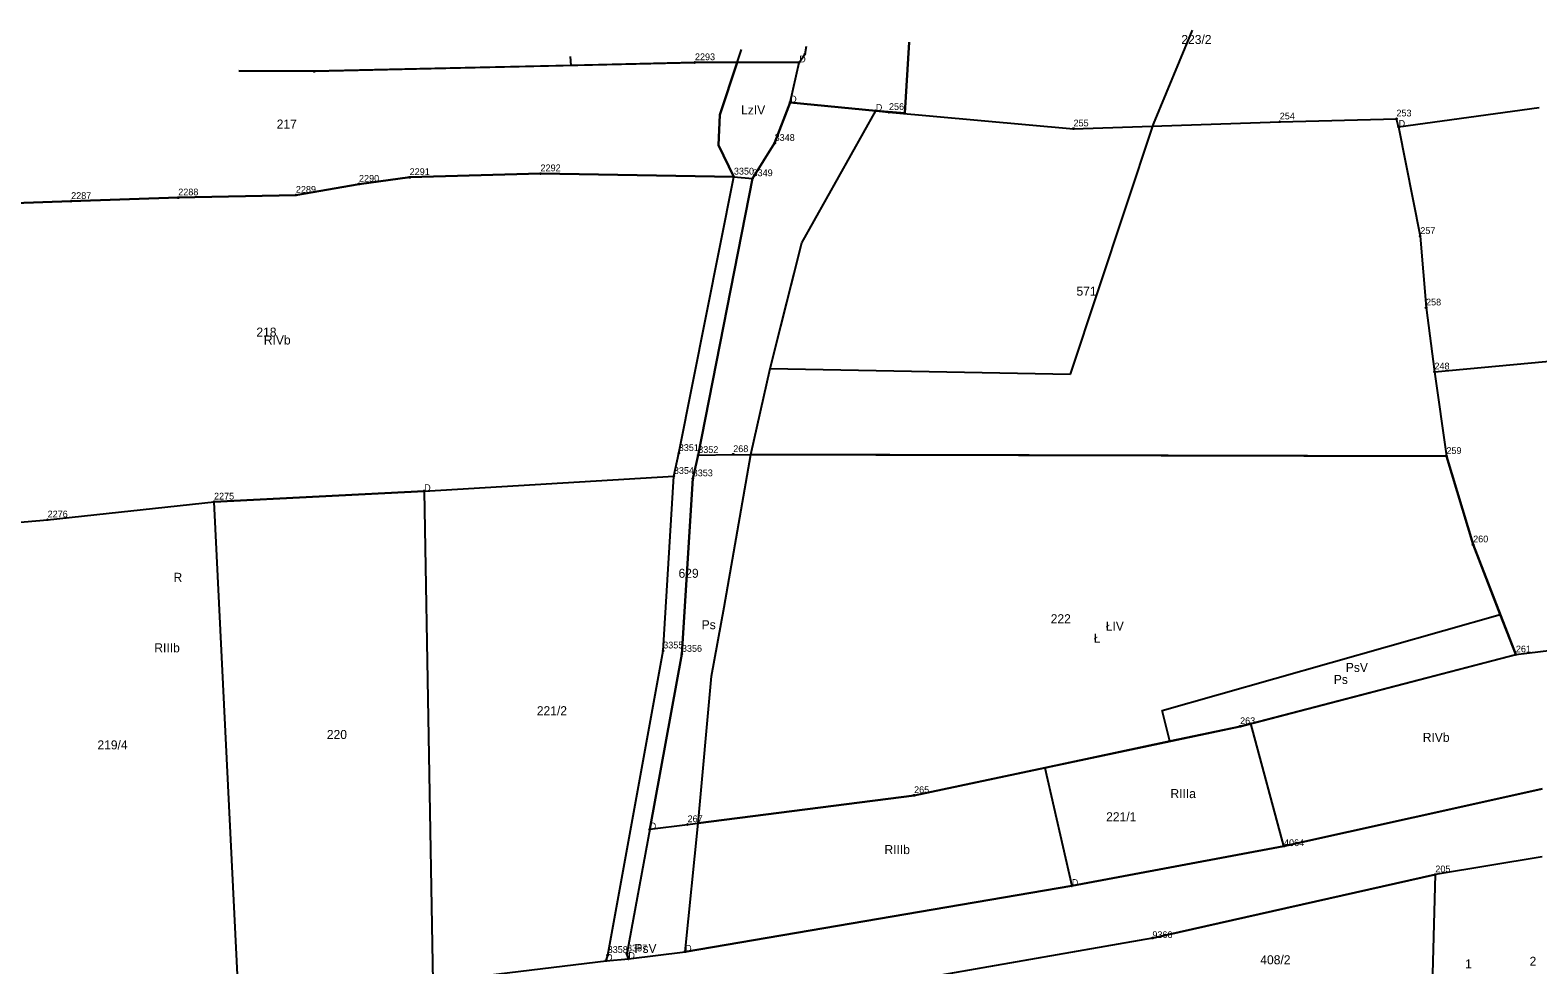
# Model space of a CAD drawing. Extents: x 7467189 to 7469366, y 5491487 to 5492734.
# Drawn here: x 7468735 to 7468985.9, y 5491680.6 to 5491836.1 of the extents above; entities that cross this region are included whole.
import ezdxf

# ---------------------------------------------------------------- set-up
doc = ezdxf.new("R2010")
doc.units = 0
for name, color, linetype in [('203-punkt graniczny', 7, 'Continuous'), ('203-punkt graniczny-Atr103', 7, 'Continuous'), ('209-oznaczenie konturu klasyfikacyjnego', 7, 'Continuous'), ('210-oznaczenie konturu użytku gruntowego', 7, 'Continuous'), ('211-numer działki ewidencyjnej', 7, 'Continuous'), ('217-kontur klasyfikacyjny', 7, 'Continuous'), ('218-kontur użytku gruntowego', 7, 'Continuous'), ('219-działka ewidencyjna', 7, 'Continuous'), ('Punkt budynku-Atr104', 7, 'Continuous')]:
    doc.layers.add(name, color=color, linetype=linetype)

# ---------------------------------------------------------------- blocks, each defined once
blk = doc.blocks.new('203')
blk.add_circle((0, 0), 0.09)

msp = doc.modelspace()

# ---------------------------------------------------------------- linework, layer by layer
at = {"layer": '217-kontur klasyfikacyjny'}
for points in [[(7468921.89, 5491820.44), (7468928.4, 5491836.08)], [(7468852.63, 5491830.7), (7468853.33, 5491832.89)], [(7468881.22, 5491834.07), (7468880.51, 5491822.25)], [(7468824.85, 5491831.68), (7468824.91, 5491830.22)], [(7468845.59, 5491830.7), (7468824.91, 5491830.22)], [(7468852.63, 5491830.7), (7468845.59, 5491830.7)], [(7468852.63, 5491830.7), (7468849.74, 5491821.99)], [(7468862.95, 5491830.71), (7468852.63, 5491830.7)], [(7468861.45, 5491824.07), (7468862.95, 5491830.71)], [(7468782.24, 5491829.24), (7468769.68, 5491829.33)], [(7468824.91, 5491830.22), (7468782.24, 5491829.24)], [(7468858.85, 5491817.28), (7468861.45, 5491824.07)], [(7468875.69, 5491822.68), (7468861.45, 5491824.07)], [(7468849.74, 5491821.99), (7468849.53, 5491816.93)], [(7468863.39, 5491800.69), (7468875.69, 5491822.68)], [(7468880.51, 5491822.25), (7468875.69, 5491822.68)], [(7468908.09, 5491778.88), (7468921.89, 5491820.44)], [(7468849.53, 5491816.93), (7468852.07, 5491811.68)], [(7468855.18, 5491811.41), (7468858.85, 5491817.28)], [(7468779.18, 5491808.65), (7468789.69, 5491810.49)], [(7468789.69, 5491810.49), (7468798.12, 5491811.6)], [(7468798.12, 5491811.6), (7468819.9, 5491812.23)], [(7468819.9, 5491812.23), (7468852.07, 5491811.68)], [(7468842.9, 5491765.7), (7468852.07, 5491811.68)], [(7468855.18, 5491811.41), (7468846.13, 5491765.38)], [(7468852.07, 5491811.68), (7468855.18, 5491811.41)], [(7468741.79, 5491807.63), (7468759.61, 5491808.22)], [(7468759.61, 5491808.22), (7468779.18, 5491808.65)], [(7468721.34, 5491806.93), (7468741.79, 5491807.63)], [(7468858.1, 5491779.82), (7468863.39, 5491800.69)], [(7468854.88, 5491765.51), (7468858.1, 5491779.82)], [(7468858.1, 5491779.82), (7468908.09, 5491778.88)], [(7468842.08, 5491761.89), (7468842.9, 5491765.7)], [(7468846.13, 5491765.38), (7468845.22, 5491761.49)], [(7468850.48, 5491740.07), (7468854.88, 5491765.51)], [(7468970.64, 5491765.2), (7468854.88, 5491765.51)], [(7468975.09, 5491750.5), (7468970.64, 5491765.2)], [(7468800.54, 5491759.42), (7468842.08, 5491761.89)], [(7468840.31, 5491732.85), (7468842.08, 5491761.89)], [(7468845.22, 5491761.49), (7468843.42, 5491732.29)], [(7468737.87, 5491754.64), (7468765.56, 5491757.63)], [(7468765.56, 5491757.63), (7468800.54, 5491759.42)], [(7468732.01, 5491754.12), (7468737.87, 5491754.64)], [(7468979.61, 5491738.87), (7468975.09, 5491750.5)], [(7468848.33, 5491728.61), (7468850.48, 5491740.07)], [(7468923.36, 5491722.88), (7468979.61, 5491738.87)], [(7468982.2, 5491732.21), (7468979.61, 5491738.87)], [(7468831.07, 5491682.2), (7468840.31, 5491732.85)], [(7468982.2, 5491732.21), (7468989.94, 5491733.19)], [(7468843.42, 5491732.29), (7468838.07, 5491703.14)], [(7468938.1, 5491720.73), (7468982.2, 5491732.21)], [(7468846.13, 5491704.18), (7468848.33, 5491728.61)], [(7468924.64, 5491717.8), (7468923.36, 5491722.88)], [(7468936.31, 5491720.27), (7468924.64, 5491717.8)], [(7468938.1, 5491720.73), (7468936.31, 5491720.27)], [(7468943.61, 5491700.35), (7468938.1, 5491720.73)], [(7468924.64, 5491717.8), (7468903.79, 5491713.39)], [(7468903.79, 5491713.39), (7468882.06, 5491708.79)], [(7468903.79, 5491713.39), (7468908.3, 5491693.74)], [(7468975.85, 5491707.51), (7468986.59, 5491709.9)], [(7468882.06, 5491708.79), (7468846.13, 5491704.18)], [(7468943.61, 5491700.35), (7468975.85, 5491707.51)], [(7468838.07, 5491703.14), (7468834.28, 5491682.45)], [(7468843.96, 5491682.79), (7468846.13, 5491704.18)], [(7468908.3, 5491693.74), (7468943.61, 5491700.35)], [(7468986.6, 5491698.59), (7468968.8, 5491695.61)], [(7468968.8, 5491695.61), (7468921.71, 5491685.05)], [(7468967.85, 5491658.42), (7468968.8, 5491695.61)], [(7468843.96, 5491682.79), (7468908.3, 5491693.74)], [(7468921.71, 5491685.05), (7468864.94, 5491675.1)], [(7468834.28, 5491682.45), (7468834.52, 5491681.59)], [(7468834.52, 5491681.59), (7468843.96, 5491682.79)], [(7468801.97, 5491677.77), (7468830.8, 5491681.29)], [(7468830.8, 5491681.29), (7468831.07, 5491682.2)]]:
    msp.add_lwpolyline(points, dxfattribs=at)
at = {"layer": '218-kontur użytku gruntowego'}
for points in [[(7468852.63, 5491830.7), (7468853.33, 5491832.89)], [(7468880.51, 5491822.25), (7468881.22, 5491834.07)], [(7468845.59, 5491830.7), (7468824.91, 5491830.22)], [(7468852.63, 5491830.7), (7468845.59, 5491830.7)], [(7468849.74, 5491821.99), (7468852.63, 5491830.7)], [(7468782.24, 5491829.24), (7468769.68, 5491829.33)], [(7468824.91, 5491830.22), (7468782.24, 5491829.24)], [(7468861.45, 5491824.07), (7468858.85, 5491817.28)], [(7468875.69, 5491822.68), (7468861.45, 5491824.07)], [(7468849.53, 5491816.93), (7468849.74, 5491821.99)], [(7468863.39, 5491800.69), (7468875.69, 5491822.68)], [(7468875.69, 5491822.68), (7468880.51, 5491822.25)], [(7468852.07, 5491811.68), (7468849.53, 5491816.93)], [(7468858.85, 5491817.28), (7468855.18, 5491811.41)], [(7468789.69, 5491810.49), (7468779.18, 5491808.65)], [(7468798.12, 5491811.6), (7468789.69, 5491810.49)], [(7468819.9, 5491812.23), (7468798.12, 5491811.6)], [(7468852.07, 5491811.68), (7468819.9, 5491812.23)], [(7468842.9, 5491765.7), (7468852.07, 5491811.68)], [(7468855.18, 5491811.41), (7468846.13, 5491765.38)], [(7468852.07, 5491811.68), (7468855.18, 5491811.41)], [(7468759.61, 5491808.22), (7468741.79, 5491807.63)], [(7468779.18, 5491808.65), (7468759.61, 5491808.22)], [(7468741.79, 5491807.63), (7468721.34, 5491806.93)], [(7468860.89, 5491790.84), (7468863.39, 5491800.69)], [(7468858.1, 5491779.82), (7468860.89, 5491790.84)], [(7468854.88, 5491765.51), (7468858.1, 5491779.82)], [(7468842.08, 5491761.89), (7468842.9, 5491765.7)], [(7468846.13, 5491765.38), (7468845.22, 5491761.49)], [(7468850.48, 5491740.07), (7468854.88, 5491765.51)], [(7468970.64, 5491765.2), (7468854.88, 5491765.51)], [(7468975.09, 5491750.5), (7468970.64, 5491765.2)], [(7468840.31, 5491732.85), (7468842.08, 5491761.89)], [(7468845.22, 5491761.49), (7468843.42, 5491732.29)], [(7468979.61, 5491738.87), (7468975.09, 5491750.5)], [(7468848.33, 5491728.61), (7468850.48, 5491740.07)], [(7468923.36, 5491722.88), (7468979.61, 5491738.87)], [(7468982.2, 5491732.21), (7468979.61, 5491738.87)], [(7468831.07, 5491682.2), (7468840.31, 5491732.85)], [(7468843.42, 5491732.29), (7468838.07, 5491703.14)], [(7468938.1, 5491720.73), (7468982.2, 5491732.21)], [(7468846.13, 5491704.18), (7468848.33, 5491728.61)], [(7468924.64, 5491717.8), (7468923.36, 5491722.88)], [(7468924.64, 5491717.8), (7468936.31, 5491720.27)], [(7468936.31, 5491720.27), (7468938.1, 5491720.73)], [(7468903.79, 5491713.39), (7468924.64, 5491717.8)], [(7468882.06, 5491708.79), (7468903.79, 5491713.39)], [(7468986.59, 5491709.9), (7468975.85, 5491707.51)], [(7468846.13, 5491704.18), (7468882.06, 5491708.79)], [(7468975.85, 5491707.51), (7468943.61, 5491700.35)], [(7468838.07, 5491703.14), (7468834.28, 5491682.45)], [(7468843.96, 5491682.79), (7468846.13, 5491704.18)], [(7468943.61, 5491700.35), (7468908.3, 5491693.74)], [(7468986.6, 5491698.59), (7468968.8, 5491695.61)], [(7468968.8, 5491695.61), (7468921.71, 5491685.05)], [(7468908.3, 5491693.74), (7468843.96, 5491682.79)], [(7468921.71, 5491685.05), (7468864.94, 5491675.1)], [(7468834.28, 5491682.45), (7468834.52, 5491681.59)], [(7468834.52, 5491681.59), (7468843.96, 5491682.79)], [(7468801.97, 5491677.77), (7468830.8, 5491681.29)], [(7468830.8, 5491681.29), (7468831.07, 5491682.2)]]:
    msp.add_lwpolyline(points, dxfattribs=at)
at = {"layer": '219-działka ewidencyjna'}
for points in [[(7468864.12, 5491833.35), (7468863.88, 5491832.1)], [(7468782.24, 5491829.24), (7468845.59, 5491830.7)], [(7468862.95, 5491830.71), (7468845.59, 5491830.7)], [(7468861.45, 5491824.07), (7468862.95, 5491830.71)], [(7468862.95, 5491830.71), (7468863.88, 5491832.1)], [(7468769.68, 5491829.33), (7468782.24, 5491829.24)], [(7468861.45, 5491824.07), (7468858.85, 5491817.28)], [(7468861.45, 5491824.07), (7468875.69, 5491822.68)], [(7468962.69, 5491820.01), (7468986.08, 5491823.2)], [(7468875.69, 5491822.68), (7468877.88, 5491822.43)], [(7468877.88, 5491822.43), (7468908.59, 5491819.69)], [(7468908.59, 5491819.69), (7468942.91, 5491820.85)], [(7468942.91, 5491820.85), (7468962.32, 5491821.35)], [(7468962.69, 5491820.01), (7468962.32, 5491821.35)], [(7468962.69, 5491820.01), (7468966.29, 5491801.81)], [(7468855.18, 5491811.41), (7468858.85, 5491817.28)], [(7468779.18, 5491808.65), (7468789.69, 5491810.49)], [(7468789.69, 5491810.49), (7468798.12, 5491811.6)], [(7468798.12, 5491811.6), (7468819.9, 5491812.23)], [(7468819.9, 5491812.23), (7468852.07, 5491811.68)], [(7468842.9, 5491765.7), (7468852.07, 5491811.68)], [(7468846.13, 5491765.38), (7468855.18, 5491811.41)], [(7468852.07, 5491811.68), (7468855.18, 5491811.41)], [(7468741.79, 5491807.63), (7468759.61, 5491808.22)], [(7468759.61, 5491808.22), (7468779.18, 5491808.65)], [(7468721.34, 5491806.93), (7468741.79, 5491807.63)], [(7468966.29, 5491801.81), (7468967.25, 5491789.92)], [(7468967.25, 5491789.92), (7468968.65, 5491779.26)], [(7468968.65, 5491779.26), (7469013.45, 5491783.38)], [(7468968.65, 5491779.26), (7468970.64, 5491765.2)], [(7468842.08, 5491761.89), (7468842.9, 5491765.7)], [(7468845.22, 5491761.49), (7468846.13, 5491765.38)], [(7468846.13, 5491765.38), (7468851.96, 5491765.52)], [(7468851.96, 5491765.52), (7468970.64, 5491765.2)], [(7468970.64, 5491765.2), (7468975.09, 5491750.5)], [(7468800.54, 5491759.42), (7468842.08, 5491761.89)], [(7468840.31, 5491732.85), (7468842.08, 5491761.89)], [(7468843.42, 5491732.29), (7468845.22, 5491761.49)], [(7468737.87, 5491754.64), (7468765.56, 5491757.63)], [(7468800.54, 5491759.42), (7468765.56, 5491757.63)], [(7468769.6, 5491676.74), (7468765.56, 5491757.63)], [(7468800.54, 5491759.42), (7468801.97, 5491677.77)], [(7468732.01, 5491754.12), (7468737.87, 5491754.64)], [(7468975.09, 5491750.5), (7468982.2, 5491732.21)], [(7468831.07, 5491682.2), (7468840.31, 5491732.85)], [(7468982.2, 5491732.21), (7468989.94, 5491733.19)], [(7468838.07, 5491703.14), (7468843.42, 5491732.29)], [(7468936.31, 5491720.27), (7468982.2, 5491732.21)], [(7468882.06, 5491708.79), (7468936.31, 5491720.27)], [(7468943.61, 5491700.35), (7468986.59, 5491709.9)], [(7468844.36, 5491703.95), (7468882.06, 5491708.79)], [(7468838.07, 5491703.14), (7468834.28, 5491682.45)], [(7468838.07, 5491703.14), (7468844.36, 5491703.95)], [(7468908.3, 5491693.74), (7468943.61, 5491700.35)], [(7468986.6, 5491698.59), (7468968.8, 5491695.61)], [(7468921.71, 5491685.05), (7468968.8, 5491695.61)], [(7468967.85, 5491658.42), (7468968.8, 5491695.61)], [(7468843.96, 5491682.79), (7468908.3, 5491693.74)], [(7468921.71, 5491685.05), (7468844.95, 5491671.6)], [(7468834.52, 5491681.59), (7468834.28, 5491682.45)], [(7468834.52, 5491681.59), (7468843.96, 5491682.79)], [(7468801.97, 5491677.77), (7468830.8, 5491681.29)], [(7468830.8, 5491681.29), (7468831.07, 5491682.2)], [(7468830.8, 5491681.29), (7468834.52, 5491681.59)]]:
    msp.add_lwpolyline(points, dxfattribs=at)

# ---------------------------------------------------------------- block references
at = {"layer": '203-punkt graniczny'}
for p in [(7468845.59, 5491830.7), (7468862.95, 5491830.71), (7468863.88, 5491832.1), (7468782.24, 5491829.24), (7468861.45, 5491824.07), (7468875.69, 5491822.68), (7468877.88, 5491822.43), (7468942.91, 5491820.85), (7468962.32, 5491821.35), (7468908.59, 5491819.69), (7468962.69, 5491820.01), (7468858.85, 5491817.28), (7468789.69, 5491810.49), (7468798.12, 5491811.6), (7468819.9, 5491812.23), (7468852.07, 5491811.68), (7468855.18, 5491811.41), (7468741.79, 5491807.63), (7468759.61, 5491808.22), (7468779.18, 5491808.65), (7468966.29, 5491801.81), (7468967.25, 5491789.92), (7468968.65, 5491779.26), (7468842.9, 5491765.7), (7468846.13, 5491765.38), (7468851.96, 5491765.52), (7468970.64, 5491765.2), (7468842.08, 5491761.89), (7468845.22, 5491761.49), (7468765.56, 5491757.63), (7468800.54, 5491759.42), (7468737.87, 5491754.64), (7468975.09, 5491750.5), (7468840.31, 5491732.85), (7468843.42, 5491732.29), (7468982.2, 5491732.21), (7468936.31, 5491720.27), (7468882.06, 5491708.79), (7468838.07, 5491703.14), (7468844.36, 5491703.95), (7468943.61, 5491700.35), (7468968.8, 5491695.61), (7468908.3, 5491693.74), (7468921.71, 5491685.05), (7468831.07, 5491682.2), (7468834.28, 5491682.45), (7468843.96, 5491682.79), (7468830.8, 5491681.29), (7468834.52, 5491681.59)]:
    msp.add_blockref('203', p, dxfattribs=at)

# ---------------------------------------------------------------- texts
at = {"layer": '203-punkt graniczny-Atr103'}
for s, height, p in [('2293', 1.125, (7468845.59, 5491831.08)), ('D', 1.12, (7468862.95, 5491830.71)), ('D', 1.12, (7468861.45, 5491824.07)), ('D', 1.12, (7468875.69, 5491822.68)), ('256', 1.125, (7468877.88, 5491822.81)), ('253', 1.125, (7468962.32, 5491821.73)), ('255', 1.125, (7468908.59, 5491820.07)), ('254', 1.125, (7468942.91, 5491821.23)), ('D', 1.12, (7468962.69, 5491820.01)), ('3348', 1.125, (7468858.85, 5491817.66)), ('2291', 1.125, (7468798.12, 5491811.98)), ('2292', 1.125, (7468819.9, 5491812.61)), ('3350', 1.125, (7468852.07, 5491812.06)), ('3349', 1.125, (7468855.18, 5491811.79)), ('2290', 1.125, (7468789.69, 5491810.87)), ('2287', 1.125, (7468741.79, 5491808)), ('2288', 1.125, (7468759.61, 5491808.6)), ('2289', 1.125, (7468779.18, 5491809.03)), ('257', 1.125, (7468966.29, 5491802.18)), ('258', 1.125, (7468967.25, 5491790.29)), ('248', 1.125, (7468968.65, 5491779.64)), ('3351', 1.125, (7468842.9, 5491766.08)), ('3352', 1.125, (7468846.13, 5491765.75)), ('268', 1.125, (7468851.96, 5491765.89)), ('259', 1.125, (7468970.64, 5491765.58)), ('3354', 1.125, (7468842.08, 5491762.27)), ('3353', 1.125, (7468845.22, 5491761.87)), ('D', 1.12, (7468800.54, 5491759.42)), ('2275', 1.125, (7468765.56, 5491758)), ('2276', 1.125, (7468737.87, 5491755.02)), ('260', 1.125, (7468975.09, 5491750.88)), ('3355', 1.125, (7468840.31, 5491733.23)), ('3356', 1.125, (7468843.42, 5491732.67)), ('261', 1.125, (7468982.2, 5491732.58)), ('263', 1.125, (7468936.31, 5491720.64)), ('265', 1.125, (7468882.06, 5491709.17)), ('267', 1.125, (7468844.36, 5491704.33)), ('D', 1.12, (7468838.07, 5491703.14)), ('4064', 1.125, (7468943.61, 5491700.35)), ('D', 1.12, (7468908.3, 5491693.74)), ('205', 1.125, (7468968.8, 5491695.99)), ('9366', 1.125, (7468921.71, 5491685.05)), ('D', 1.12, (7468830.8, 5491681.29)), ('3358', 1.125, (7468831.07, 5491682.58)), ('3357', 1.125, (7468834.28, 5491682.83)), ('D', 1.12, (7468834.52, 5491681.59)), ('D', 1.12, (7468843.96, 5491682.79))]:
    msp.add_text(s, height=height, dxfattribs=at).set_placement(p)
at = {"layer": '209-oznaczenie konturu klasyfikacyjnego'}
for s, p in [('LzIV', (7468853.27, 5491822.06)), ('RIVb', (7468773.85, 5491783.79)), ('ŁIV', (7468913.95, 5491736.21)), ('RIIIb', (7468755.63, 5491732.58)), ('PsV', (7468953.9, 5491729.32)), ('RIVb', (7468966.7, 5491717.69)), ('RIIIa', (7468924.72, 5491708.34)), ('RIIIb', (7468877.13, 5491699.02)), ('PsV', (7468835.52, 5491682.59))]:
    msp.add_text(s, height=1.5, dxfattribs=at).set_placement(p)
at = {"layer": '210-oznaczenie konturu użytku gruntowego'}
for s, p in [('R', (7468758.82, 5491744.31)), ('Ps', (7468846.71, 5491736.43)), ('Ł', (7468911.95, 5491734.21)), ('Ps', (7468951.9, 5491727.32))]:
    msp.add_text(s, height=1.5, dxfattribs=at).set_placement(p)
at = {"layer": '211-numer działki ewidencyjnej'}
for s, p in [('223/2', (7468926.53, 5491833.78)), ('217', (7468775.99, 5491819.71)), ('571', (7468909.08, 5491791.91)), ('218', (7468772.61, 5491785.1)), ('629', (7468842.86, 5491744.98)), ('222', (7468904.79, 5491737.42)), ('221/2', (7468819.28, 5491722.12)), ('219/4', (7468746.16, 5491716.44)), ('220', (7468784.34, 5491718.17)), ('221/1', (7468914.02, 5491704.48)), ('408/2', (7468939.67, 5491680.69))]:
    msp.add_text(s, height=1.5, dxfattribs=at).set_placement(p)
at = {"layer": 'Punkt budynku-Atr104'}
for s, p in [('1', (7468973.75, 5491680)), ('2', (7468984.48, 5491680.44))]:
    msp.add_text(s, height=1.5, dxfattribs=at).set_placement(p)

doc.saveas('drawing.dxf')
